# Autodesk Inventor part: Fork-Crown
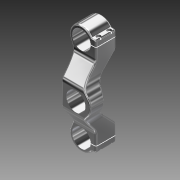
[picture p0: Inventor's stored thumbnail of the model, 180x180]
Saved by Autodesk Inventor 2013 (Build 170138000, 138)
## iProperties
Shininess: 64.0
Length Units: 11272
Angle Units: 11279
Time Units: 11290
Mass Units: 11286
Length Display Precision: 3
Angle Display Precision: 2
Compacted: True
Created: 2001-11
Part Number: Fork-Crown
Document SubType Name: Modeling
Designer: Autodesk, Inc.
Mass: 96.1049 g
Surface Area: 286.05 cm^2
Volume: 96.1049 cm^3
Density: 1 g/cm^3
Material: Generic
Density: 0.0
Volumn: 0.0
Area: 0.0
PropertySet Name: Model Information
Control State: 0
Master: False
Checked Out: False
Author: Autodesk, Inc.
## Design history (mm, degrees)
sketch "Sketch1"
  geometry: L1 (387.107, 198.738)-(394.972, 198.738); L2 (387.081, 199.805)-(394.972, 199.805); L3 (394.972, 205.703)-(394.972, 199.805); L4 (390.064, 208.878)-(391.797, 208.878); L5 (362.993, 135.224)-(362.993, 160.563); L6 (394.972, 198.738)-(394.972, 166.433); L7 (362.993, 135.224)-(406.863, 135.224); L8 (362.993, 135.224)-(362.993, 109.884); L9 (387.081, 70.642)-(394.972, 70.642); L10 (394.972, 64.744)-(394.972, 70.642); L11 (390.064, 61.569)-(391.797, 61.569); L12 (387.107, 71.709)-(394.972, 71.709); L13 (394.972, 71.709)-(394.972, 104.014); A1 r 13.97 centre (373.138, 198.936) between (387.081, 199.805) and (387.107, 198.738); A2 r 3.175 centre (391.797, 205.703) between (394.972, 205.703) and (391.797, 208.878); A3 r 3.048 centre (390.064, 211.926) between (387.646, 210.07) and (390.064, 208.878); A4 r 18.288 centre (373.138, 198.936) between (387.646, 210.07) and (356.426, 191.509); A5 r 76.2 centre (286.793, 160.563) between (362.993, 160.563) and (356.426, 191.509); A6 r 25.4 centre (420.372, 166.433) between (394.972, 166.433) and (401.412, 149.532); A7 r 21.504 centre (385.359, 135.224) between (406.863, 135.224) and (401.412, 149.532); A8 r 76.2 centre (286.793, 109.884) between (356.426, 78.938) and (362.993, 109.884); A9 r 18.288 centre (373.138, 71.511) between (356.426, 78.938) and (387.646, 60.377); A10 r 3.175 centre (391.797, 64.744) between (391.797, 61.569) and (394.972, 64.744); A11 r 3.048 centre (390.064, 58.521) between (390.064, 61.569) and (387.646, 60.377); A12 r 13.97 centre (373.138, 71.511) between (387.107, 71.709) and (387.081, 70.642); A13 r 25.4 centre (420.372, 104.014) between (401.412, 120.915) and (394.972, 104.014); A14 r 21.504 centre (385.359, 135.224) between (401.412, 120.915) and (406.863, 135.224)
  constraints: 28 point on circle, 26 end point, 18 symmetric about line, 14 centre point, 8 tangent, 3 horizontal, 3 vertical, 1 collinear, 1 concentric, 1 horizontal alignment, 1 perpendicular, 15 other
  dimensions: "d1" = 13.97 radius of A1; "d7" = 76.2 radius of A5; "d9" = 18.288 radius of A4; "d92" = 3.175 radius of A2; "d94" = 5.89767 distance from line of A2.centre L2; "d95" = 1.06735 distance between parallel lines of L2 L1; "d99" = 12.2212 horizontal distance of A7.centre A1.centre; "d100" = 25.4 radius of A6; "d101" = 21.50376 radius of A7; "d102" = 3.048 radius of A3; "d103" = 25.33944 distance of L5.start L5.end; "d104" = 43.87007 distance of L5.start L7.end
extrude "ExtrusionBlind1" new body sketch "Sketch1" distance "d16" = 76.2; taper "d17" = 0 deg
node "WorkPlane1"
workaxis "Work Axis4"
sketch "Sketch9"
  geometry: L1 (28.214, 35.429)-(47.471, 16.806); L2 (47.471, 16.806)-(82.009, 16.806); L3 (82.009, 47.286)-(45.305, 47.286); L4 (45.305, 47.286)-(19.099, 67.761); L5 (19.099, 67.761)-(0.009, 67.761); L6 (0.009, 45.941)-(0.009, 67.761); L7 (0.009, -15.24)-(0.009, 91.44) reference; L8 (25.348, 76.2)-(-25.331, 76.2) reference; L9 (82.009, 0)-(82.009, 76.2) reference; L10 (-25.331, 0)-(25.348, 0) reference; L11 (-28.197, 35.429)-(-47.454, 16.806); L12 (-45.288, 47.286)-(-19.081, 67.761); L13 (-19.081, 67.761)-(0.009, 67.761); L14 (0.009, 45.941)-(0.009, 67.761); L15 (-81.992, 47.286)-(-45.288, 47.286); L16 (-47.454, 16.806)-(-81.992, 16.806); L17 (-81.992, 0)-(-81.992, 76.2) reference; A1 r 37.592 centre (2.081, 8.406) between (28.214, 35.429) and (0.009, 45.941); A2 r 37.592 centre (-2.064, 8.406) between (0.009, 45.941) and (-28.197, 35.429)
  constraints: 24 end point, 5 point on line, 5 symmetric about line, 4 point on circle, 3 horizontal, 2 centre point, 1 tangent, 1 vertical, 7 other
  dimensions: "d26" = 30.48 vertical distance of L1.end L3.end; "d30" = 37.592 radius of A1; "d105" = 8.43916 distance between parallel lines of L5 L8; "d106" = 8.40601 distance from line of L10 A1.centre; "d108" = 142 deg angle of L4 L5; "d109" = 19.09001 distance of L4.end L5.end; "d110" = 20.47486 distance between parallel lines of L5 L3; "d111" = 135.959 deg angle of L2 L1
extrude "ExtrusionThru1" sketch "Sketch9" stored distance "d35" = 3.302; taper "d36" = 0 deg
fillet "Fillet1" dims "d38" = 12.7
fillet "Fillet3" dims "d73" = 6.35
sketch "Sketch15"
  geometry: L1 (6.35, -28.694)-(6.35, -5.08); L2 (6.35, -5.08)-(29.21, -5.08); L3 (0, 16.052)-(0, 0) reference; L4 (35.262, 0)-(0, 0) reference; A1 r 19.05 centre (9.613, -47.462) between (22.86, -33.772) and (6.35, -28.694); A2 r 76.2 centre (99.038, -35.583) between (29.21, -5.08) and (22.86, -33.772); A3 r 21.504 centre (9.613, -47.462) between (-6.439, -33.154) and (-6.439, -61.771) reference; 3 further points
  constraints: 4 end point, 4 point on circle, 2 centre point, 1 coincident, 1 perpendicular, 2 other
  dimensions: "d113" = 6.35 distance between parallel lines of L1 L3; "d114" = 5.08 distance between parallel lines of L4 L2; "d115" = 76.2 radius of A2; "d116" = 22.86 distance of L1.end L2.end; "d117" = 19.05 radius of A1; "d118" = 6.35 horizontal distance of A1.start L2.end
extrude "Extrusion4" cut sketch "Sketch15" distance "d75" = 25.4; taper "d76" = 0 deg
fillet "Fillet5" dims "d77" = 5.08
workplane "Work Plane5"
mirror "Mirror1"
sketch "Sketch16"
  geometry: L1 (-22.366, 14.717)-(15.696, 14.717) reference; L2 (-22.366, 14.717)-(-22.366, -14.717) reference; L3 (15.696, -14.717)-(-22.366, -14.717) reference; A1 r 25.4 centre (35.013, -31.21) between (16.052, -14.309) and (15.696, -14.717) reference; A2 r 21.504 centre (0, 0) between (16.052, -14.309) and (16.052, 14.309) reference; A3 r 25.4 centre (35.013, 31.21) between (15.696, 14.717) and (16.052, 14.309) reference
hole "Hole6" sketch "Sketch16" at (0, 0) diameter "d80" = 28.575; stored, may be unused: countersink angle "d84" = 82 deg, drill point angle "d86" = 118 deg; dims "d81" = 12.7, "d82" = 9.525, "d83" = 6.35, "d85" = 19.05
fillet "Fillet6" dims "d120" = 2.54
workplane "Work Plane6"
sketch "Sketch18"
  geometry: L1 (-21.834, 19.346)-(-21.834, 44.746) reference; 2 further points
  constraints: 1 vertical alignment
  dimensions: "d121" = 15.875 distance of point (-18.659, 24.052) point (-18.659, 39.927); "d129" = 3.175 distance from line of point (-18.659, 39.927) L1
hole "Hole7" sketch "Sketch18" at (-18.659, 39.927), (-18.659, 24.052) diameter "d122" = 3.2512; stored, may be unused: countersink angle "d126" = 82 deg, drill point angle "d128" = 118 deg; dims "d123" = 12.7, "d124" = 6.35, "d125" = 11.43, "d127" = 25.4
mirror "Mirror2"
body "Solid1"
node "Projected Loop1"
other parameters: "mdtd132" = 1.3 [user parameter], "mdtd133" = 3.8 [user parameter], "mdtd136" = 1 [user parameter], "d0" = 14.732 (derived), "d2" = 127 (derived), "d4" = 20.574 (derived), "d6" = 76.2 (derived), "d8" = 18.288 (derived), "d10" = 1.016 (derived), "d12" = 25.4 (derived), "d14" = 23.622 (derived), "d18" = 0, "d19" = 0, "d20" = 0, "d21" = 0, "d22" = 0, "d23" = 0, "d25" = 30.48 (derived), "d27" = 38.354 (derived), "d29" = 37.592 (derived), "d31" = 50.8 (derived), "d33" = 142 deg (derived), "d37" = 0, "d39" = 0, "Hole" = 28.575 [user parameter], "d119" = 0
